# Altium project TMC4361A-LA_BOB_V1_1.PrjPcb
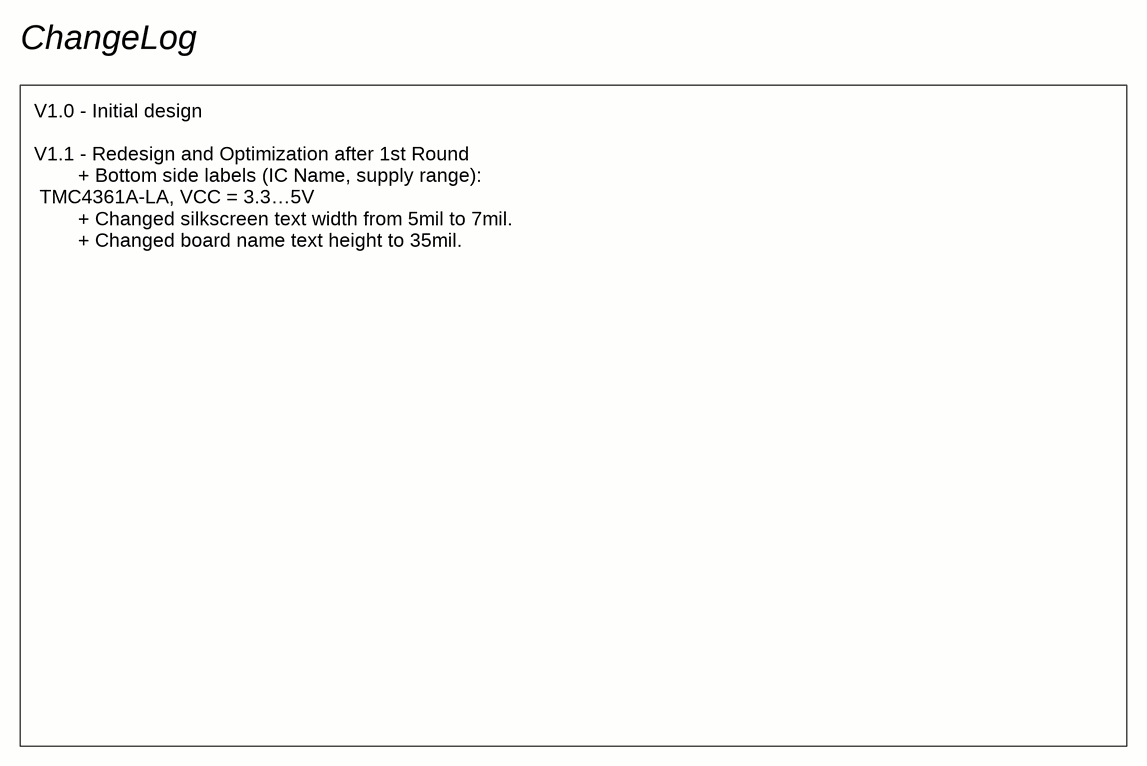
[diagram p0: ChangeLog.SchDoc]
BoardName: TMC4361A-LA; BoardVersion: 1.1; Chip: TMC4361A-LA; VCC: 3.3...5V
2 sheets, 21 parts. Net scope: global (net labels, ports and power ports of the same name join across sheets).
Board file: TMC4361A-LA_BOB_V1_1.PcbDoc
Sheets:
  ChangeLog.SchDoc
  TMC4361A-LA_BOB_V1_1.SchDoc

## Sheet ChangeLog.SchDoc
size A4

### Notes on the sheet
- ChangeLog
- V1.0 - Initial design
  V1.1 - Redesign and Optimization after 1st Round
  + Bottom side labels (IC Name, supply range):
  TMC4361A-LA, VCC = 3.3…5V
  + Changed silkscreen text width from 5mil to 7mil.
  + Changed board name text height to 35mil.

## Sheet TMC4361A-LA_BOB_V1_1.SchDoc
size A4
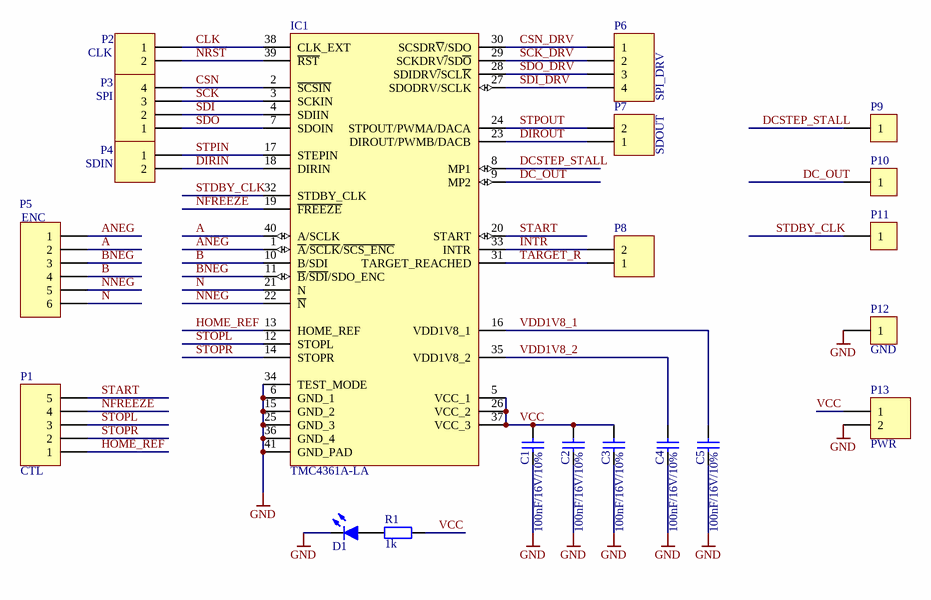
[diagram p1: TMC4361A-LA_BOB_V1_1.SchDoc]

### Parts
C1  100nF/16V/10%  [C0603]
C2  100nF/16V/10%  [C0603]
C3  100nF/16V/10%  [C0603]
C4  100nF/16V/10%  [C0603]
C5  100nF/16V/10%  [C0603]
D1  LED, Blue, SMD, 20mA, 2.8V, 465 nm  [LED_0603]  (value not drawn)
IC1  TMC4361A-LA  [TMC4361A-LA_QFN40_0.5_6.0X6.0]
P1  CTL  [5_PIN_THT]
P2  CLK  [2_PIN_THT]
P3  SPI  [4_PIN_THT]
P4  SDIN  [2_PIN_THT]
P5  ENC  [6_PIN_THT]
P6  SPI_DRV  [4_PIN_THT]
P7  SDOUT  [2_PIN_THT]
P8  (no value)  [2_PIN_THT]
P9  DCSTEP_STALL  [TH_PIN]  (value not drawn)
P10  DC_OUT  [TH_PIN]  (value not drawn)
P11  STDBY_CLK  [TH_PIN]  (value not drawn)
P12  GND  [TH_PIN]
P13  PWR  [2_PIN_THT]
R1  1k  [R0603]

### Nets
GND: C1.2 C2.2 C3.2 C4.2 C5.2 D1.2(K) IC1.6(GND_1) IC1.15(GND_2) IC1.25(GND_3) IC1.34(TEST_MODE) IC1.36(GND_4) IC1.41(GND_PAD) P12.1 P13.2
A: IC1.40(A/SCLK) P5.2
ANEG: IC1.1(~{A}/~{SCLK}/~{SCS_ENC}) P5.1
B: IC1.10(B/SDI) P5.4
BNEG: IC1.11(~{B}/~{SDI}/SDO_ENC) P5.3
CLK: IC1.38(CLK_EXT) P2.1
CSN: IC1.2(~{SCSIN}) P3.4
CSN_DRV: IC1.30(SCSDR~{V}/SDO) P6.1
DC_OUT: IC1.9(MP2) P10.1
DCSTEP_STALL: IC1.8(MP1) P9.1
DIRIN: IC1.18(DIRIN) P4.2
DIROUT: IC1.23(DIROUT/PWMB/DACB) P7.1
HOME_REF: IC1.13(HOME_REF) P1.1
INTR: IC1.33(INTR) P8.2
N: IC1.21(N) P5.6
NFREEZE: IC1.19(~{FREEZE}) P1.4
NNEG: IC1.22(~{N}) P5.5
NRST: IC1.39(~{RST}) P2.2
SCK: IC1.3(SCKIN) P3.3
SCK_DRV: IC1.29(SCKDRV~{/}SD~{O}) P6.2
SDI: IC1.4(SDIIN) P3.2
SDI_DRV: IC1.27(SDODRV/SCLK) P6.4
SDO: IC1.7(SDOIN) P3.1
SDO_DRV: IC1.28(SDIDRV~{/}SCL~{K}) P6.3
START: IC1.20(START) P1.5
STDBY_CLK: IC1.32(STDBY_CLK) P11.1
STOPL: IC1.12(STOPL) P1.3
STOPR: IC1.14(STOPR) P1.2
STPIN: IC1.17(STEPIN) P4.1
STPOUT: IC1.24(STPOUT/PWMA/DACA) P7.2
TARGET_R: IC1.31(TARGET_REACHED) P8.1
VCC: C1.1 C2.1 C3.1 IC1.5(VCC_1) IC1.26(VCC_2) IC1.37(VCC_3) P13.1 R1.2
VDD1V8_1: C5.1 IC1.16(VDD1V8_1)
VDD1V8_2: C4.1 IC1.35(VDD1V8_2)
NetD1_1: D1.1(A) R1.1

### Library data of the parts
C1-C5 = Capacitor: Ceramic capacitor; MPN: MC0603B104K160CT; Type: MLCC; VoltageRating: 16V; ComponentLinknDescription: Datasheet; MF: Multicomp; Capacitance: 100nF; Precision: 10%
D1 = LED, Blue, SMD, 20mA, 2.8V, 465 nm: MPN: LTST-C191TBKT-5A; MF: Lite-On
IC1 = TMC4361A-LA: S-ramp motion controller for stepper motors with high velocities. With SPI and Step/Dir; QFN40(5x5); Geometry.Height: 0.9mm; MF: TRINAMIC
P1 = Header 5: Header, 5-Pin; Fitted: Not fitted
P2 P4 P7 P8 P13 = Header 2: Header, 2-Pin; Fitted: Not fitted
P3 P6 = Header 4: Header, 4-Pin; Fitted: Not fitted
P5 = Header 6: Header, 6-Pin; Fitted: Not fitted
P9-P12 = PIN: Note: n.b; Fitted: Not fitted
R1 = 1 kohm, 50 V, 0603 [1608 Metric], 63 mW, ± 1%, MC Series: MPN: MC0063W060311K; VoltageRating: 50V; Temp coefficient: *ppm; PowerRating: 63mW; MF: MULTICOMP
